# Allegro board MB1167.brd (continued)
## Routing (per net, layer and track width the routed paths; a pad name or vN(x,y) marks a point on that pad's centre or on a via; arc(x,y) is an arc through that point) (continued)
PB6: length 159.7
  TOP w0.127: v1(113.54,145.8) CN6.18 116.59,145.8 117.5,146.71 117.5,148.23 119.51,150.24 119.51,158.12 v1(122.43,161.04) ; R43.2 91.57,136.78 92.1,137.31 v1(92.1,137.85) ; v1(33.66,151.51) U3.7
  L4_SIG w0.102: v1(92.1,137.85) 92.1,138.84 92.58,139.32 92.58,140.21 95.12,142.75 96.39,142.75 97.28,143.64 108.08,143.64 110.87,146.43 112.9,146.43 v1(113.54,145.8)
  BOTTOM w0.127: v1(122.43,161.04) 117.86,165.61 117.86,167.89 115.09,170.66 42.27,170.66 39.88,168.28 39.88,161.67 35.81,157.61 35.81,152.4 R226.2 v1(33.66,151.51)
PB7: length 202.9
  TOP w0.127: U4.B5 83.3,139.69 83.69,140.08 84.33,140.08 84.58,139.83 85.22,139.83 85.47,139.57 87.51,139.57 v5(87.95,139.13) ; v1(88.39,56.13) 92.25,56.13 93.01,55.37 111.38,55.37 R301.2 112.27,52.45 111.38,51.56 ; v1(112.67,145.8) 112.67,144.17 112.27,143.76 111.56,143.76 111.05,143.26 CN6.21 ; v1(129.74,137.9) 129.97,138.13 129.97,145.8 128.8,146.96 v1(128.02,146.96)
  L4_SIG w0.102: v1(128.02,146.96) 123.47,146.96 121.72,145.21 113.33,145.21 112.75,145.8 v1(112.67,145.8) 111,145.8 106.81,141.6 97.03,141.6 92.84,137.41 89.92,137.41 88.27,139.06 88.01,139.06 v5(87.95,139.13) ; v1(88.39,56.13) 88.39,56.64 88.9,57.15 90.02,57.15 106.25,73.38 106.25,74.42 107.34,75.51 108.34,75.51 111.56,78.73 111.56,88.54 116.1,93.09 117.63,93.09 124.59,100.05 124.59,100.94 125.81,102.16 127.23,102.16 127.81,102.74 127.81,104.44 126.7,105.56 126.57,105.56 124.79,107.34 124.79,111.05 127.81,114.07 132.03,114.07 132.66,114.71 132.66,127.2 130.99,128.88 130.99,136.73 129.82,137.9 v1(129.74,137.9)
PB8: length 453.9
  TOP w0.127: v1(69.53,29.27) CN20.40 69.53,24.57 R190.2 ; v1(40.39,161.29) 40.64,161.54 R5.1 ; CN6.31 108.33,136.91 v1(108.08,136.65) 107.06,135.64 99.11,135.64 96.7,133.22 89.11,133.22 88.27,134.07 88.27,135.76 86.87,137.16 85.22,137.16 84.29,138.09 U4.A7 ; R195.1 123.19,23.11 123.19,24.64 122.94,24.89 122.17,24.89 v1(121.41,25.65)
  L4_SIG w0.102: v1(69.53,29.27) 69.53,34.28 68.83,34.98 53.8,34.98 53.47,35.31 v1(53.47,35.69) 53.47,36.42 54.42,37.38 75.39,37.38 116.64,78.63 116.64,86.94 131.42,101.73 131.42,106.1 133.83,108.51 136.07,108.51 141.22,113.67 142.93,113.67 146.3,117.04 153.67,117.04 155.57,118.95 155.57,134.11 154.18,135.51 154.18,146.81 151.89,149.1 151.89,153.16 v1(150.5,154.56) 150.11,154.94 150.11,156.97 147.7,159.38 127.13,159.38 126.36,160.15 121.79,160.15 119.63,162.31 108.58,162.31 106.3,160.02 103.5,160.02 103,159.51 v1(102.74,159.51) 102.49,159.51 100.46,157.48 98.81,157.48 97.66,158.62 96.39,158.62 94.36,160.66 83.44,160.66 81.92,162.18 66.55,162.18 65.79,161.42 40.51,161.42 v1(40.39,161.29)
  BOTTOM w0.127: v1(69.53,29.27) 69.53,28.77 75.95,22.35 94.74,22.35 96.01,23.62 118.75,23.62 120.78,25.65 v1(121.41,25.65) ; R290.1 53.72,35.43 v1(53.47,35.69) ; R183.1 148.21,154.6 T4.3 150.37,154.69 v1(150.5,154.56) ; v1(108.08,136.65) 107.57,137.16 107.57,154.05 105.03,156.59 105.03,158.24 103.76,159.51 v1(102.74,159.51)
PB9: length 411.9
  TOP w0.127: R191.2 70.8,24.45 CN20.38 v1(70.8,29.15) ; v5(86.49,140.68) 86.25,140.45 85.23,140.45 84.79,140.89 83.61,140.89 U4.B4 ; R3.1 v1(40.64,167.39) ; R189.1 127.33,24.97 v1(127.33,24.89) ; v1(113.54,148.34) CN6.14 116.97,148.34 119.13,150.5 119.13,158.5 v1(121.67,161.04)
  L4_SIG w0.089: 118.87,31.5 120.4,29.97
  L4_SIG w0.102: v1(121.67,161.04) 122.17,160.53 126.62,160.53 127.38,159.77 148.34,159.77 149.22,158.88 150.5,158.88 151.96,157.42 151.96,155.89 v1(151,154.94) ; v1(127.33,24.89) 125.83,26.39 124.43,26.39 122.07,28.75 121.62,28.75 120.4,29.97 ; v1(70.8,29.15) 70.8,29.65 69.98,30.48 69.98,34.42 69.14,35.26 54.56,35.26 v1(54.1,35.71) ; v5(86.49,140.68) 87.15,141.35 88.39,141.35 90.93,143.89 92.2,143.89 95.76,147.45 109.22,147.45 110.74,148.97 112.9,148.97 v1(113.54,148.34) ; 118.87,31.5 115.82,34.54 115.82,37.47 115.24,38.05 115.24,46.02 117.86,48.64 117.86,74.17 v1(116.59,75.44)
  BOTTOM w0.127: v1(127.33,24.89) 124.69,27.53 121.56,27.53 118.16,24.13 95.5,24.13 94.11,22.73 76.2,22.73 70.8,28.13 v1(70.8,29.15) ; v1(121.67,161.04) 117.35,165.35 117.35,167.64 114.81,170.18 43.43,170.18 v1(40.64,167.39) ; R298.1 152.53,154.35 T5.3 151.13,154.81 v1(151,154.94) ; R291.1 54.1,33.4 54.48,33.78 54.48,35.31 54.1,35.69 v1(54.1,35.71) ; v1(113.54,148.34) 113.77,148.34 117.08,145.02 117.08,144.28 123.7,137.67 123.7,118.59 116.79,111.68 116.79,75.69 116.59,75.49 v1(116.59,75.44)
PB10: length 110.3
  TOP w0.127: v1(43.36,135.56) 43.28,135.64 CN5.33 ; v5(73.21,133.69) U4.P12 ; R102.2 v1(34.8,107.57)
  L4_SIG w0.102: v5(73.21,133.69) 73.21,133.72 72.64,134.29 68.35,134.29 66.73,132.66 56.26,132.66 53.77,135.15 48.59,135.15 48.18,135.56 v1(43.36,135.56) 43.13,135.56 43,135.69 43,137.54 42.88,137.67 39.34,137.67 39.22,137.54 39.22,137.35 39.34,137.22 42.34,137.22 42.47,137.1 42.47,136.94 42.34,136.82 39.34,136.82 39.22,136.69 39.22,136.54 39.34,136.41 42.37,136.41 42.49,136.28 42.49,136.13 42.37,136 39.34,136 39.22,135.88 39.22,135.68 39.34,135.56 42.34,135.56 42.47,135.43 42.47,135.28 42.34,135.15 39.4,135.15 39.27,135.02 39.27,134.87 39.4,134.74 42.29,134.74 42.42,134.62 42.42,134.47 42.29,134.34 39.45,134.34 39.32,134.21 39.32,134.01 39.45,133.88 42.37,133.88 42.47,133.78 42.47,133.58 42.37,133.47 39.39,133.47 39.27,133.36 39.27,133.19 39.39,133.07 42.37,133.07 42.47,132.97 42.47,132.76 42.37,132.66 40.16,132.66 40.03,132.54 40.03,128.93 39.9,128.8 39.34,128.8 39.22,128.68 39.22,112.06 34.8,107.65 v1(34.8,107.57)
PB11: length 111.2
  TOP w0.127: v1(34.8,106.17) 35.43,105.54 R106.2 ; CN5.36 45.75,134.37 45.09,135.03 v1(44.25,135.03) ; v5(72.41,132.89) U4.R13
  L4_SIG w0.102: v1(34.8,106.17) 35.18,106.17 35.31,106.3 35.31,107.64 39.57,111.91 39.57,128.3 39.7,128.42 40.28,128.42 40.41,128.55 40.41,131.29 40.51,131.4 43.06,131.4 43.18,131.52 43.18,131.68 43.06,131.8 40.51,131.8 40.41,131.9 40.41,132.16 40.54,132.28 42.72,132.28 43.03,132.59 44.6,132.59 44.73,132.71 44.73,132.89 44.6,133.02 42.98,133.02 42.85,133.15 42.85,134.9 42.98,135.03 v1(44.25,135.03) 44.37,135.15 45.7,135.15 45.82,135.03 45.82,134.49 45.93,134.37 46.1,134.37 46.22,134.49 46.22,135.06 46.34,135.18 46.51,135.18 46.63,135.06 46.63,134.51 46.75,134.39 46.92,134.39 47.03,134.51 47.03,135.03 47.15,135.15 47.32,135.15 47.44,135.03 47.44,134.51 47.56,134.39 47.73,134.39 47.85,134.51 47.85,134.96 47.97,135.08 48.13,135.08 48.25,134.96 48.25,134.49 48.37,134.37 48.54,134.37 48.66,134.49 48.66,134.65 48.76,134.75 48.96,134.75 49.07,134.65 49.07,134.13 49.19,134.01 49.35,134.01 49.47,134.13 49.47,134.65 49.57,134.75 49.78,134.75 49.88,134.65 49.88,133.39 50,133.27 50.17,133.27 50.29,133.39 50.29,134.65 50.39,134.75 50.59,134.75 50.69,134.65 50.69,132.76 50.81,132.64 50.98,132.64 51.1,132.76 51.1,134.65 51.2,134.75 51.4,134.75 51.5,134.65 51.5,132.64 51.63,132.51 51.84,132.51 51.97,132.64 51.97,134.62 52.1,134.75 52.3,134.75 52.43,134.62 52.43,132.56 52.55,132.44 52.79,132.44 52.92,132.56 52.92,134.57 53.05,134.7 53.26,134.7 53.39,134.57 53.39,132.41 53.52,132.28 68.12,132.28 68.25,132.41 68.25,133.73 68.38,133.86 68.61,133.86 68.71,133.76 68.71,132.72 68.81,132.61 69.01,132.61 69.11,132.72 69.11,133.76 69.22,133.86 69.42,133.86 69.52,133.76 69.52,132.72 69.62,132.61 69.82,132.61 69.93,132.72 69.93,133.76 70.03,133.86 70.23,133.86 70.33,133.76 70.33,132.72 70.43,132.61 70.64,132.61 70.74,132.72 70.74,133.76 70.84,133.86 71.04,133.86 71.15,133.76 71.15,132.72 71.25,132.61 71.45,132.61 71.55,132.72 71.55,133.76 71.65,133.86 72.28,133.86 72.41,133.73 v5(72.41,132.89)
PB12: length 112.1
  TOP w0.127: v5(75.61,132.89) U4.L13 ; CN5.41 43.15,130.56 v1(43.41,130.3) ; R109.2 v1(34.8,104.9)
  L4_SIG w0.102: v1(34.8,104.9) 35.66,104.9 35.79,105.03 35.79,107.62 39.93,111.76 39.93,127.91 40.06,128.04 40.72,128.04 40.84,128.17 40.84,130.89 40.97,131.01 42.85,131.01 42.98,130.89 42.98,130.71 42.85,130.58 41.45,130.58 41.33,130.45 41.33,130.28 41.45,130.15 43.26,130.15 v1(43.41,130.3) 44.02,130.3 44.53,129.79 49.15,129.79 49.86,129.08 51.08,129.08 51.18,128.98 51.18,127.69 51.28,127.58 51.49,127.58 51.59,127.69 51.59,128.98 51.69,129.08 51.89,129.08 51.99,128.98 51.99,127.69 52.1,127.58 52.3,127.58 52.4,127.69 52.4,128.98 52.5,129.08 52.71,129.08 52.81,128.98 52.81,127.69 52.91,127.58 53.11,127.58 53.21,127.69 53.21,128.98 53.32,129.08 53.52,129.08 53.62,128.98 53.62,127.69 53.72,127.58 53.92,127.58 54.03,127.69 54.03,128.98 54.13,129.08 54.33,129.08 54.43,128.98 54.43,127.69 54.53,127.58 54.74,127.58 54.84,127.69 54.84,128.98 54.94,129.08 55.14,129.08 55.25,128.98 55.25,127.69 55.35,127.58 55.55,127.58 55.65,127.69 55.65,128.98 55.75,129.08 55.96,129.08 56.06,128.98 56.06,127.69 56.16,127.58 56.36,127.58 56.46,127.69 56.46,128.98 56.57,129.08 56.77,129.08 56.87,128.98 56.87,127.69 56.97,127.58 57.18,127.58 57.28,127.69 57.28,128.98 57.38,129.08 57.58,129.08 57.68,128.98 57.68,127.69 57.79,127.58 57.99,127.58 58.09,127.69 58.09,128.98 58.19,129.08 58.4,129.08 58.5,128.98 58.5,127.69 58.6,127.58 58.8,127.58 58.9,127.69 58.9,128.98 59,129.08 59.21,129.08 59.31,128.98 59.31,127.69 59.41,127.58 59.61,127.58 59.72,127.69 59.72,128.98 59.82,129.08 60.02,129.08 60.12,128.98 60.12,127.69 60.22,127.58 60.43,127.58 60.53,127.69 60.53,128.98 60.63,129.08 62.5,129.08 65.34,126.24 71.25,126.24 75.61,130.6 v5(75.61,132.89)
  BOTTOM w0.127: v1(43.41,130.3) 42.42,130.3 42.16,130.56
PB13: length 110.5
  TOP w0.127: R115.2 v1(34.8,103.63) ; U4.K14 76.44,132.12 76.44,130.53 v5(76.34,130.43) ; CN5.43 v1(43.41,129.29)
  L4_SIG w0.102: v1(34.8,103.63) 35.56,103.63 36.2,104.27 36.2,107.52 40.28,111.61 40.28,126.24 40.39,126.34 42.72,126.34 42.82,126.44 42.82,126.64 42.72,126.75 40.39,126.75 40.28,126.85 40.28,127.08 40.41,127.2 43,127.2 43.13,127.33 43.13,127.51 43,127.64 41.22,127.64 41.1,127.75 41.1,127.92 41.22,128.04 42.83,128.04 42.95,128.16 42.95,128.33 42.83,128.45 41.35,128.45 41.25,128.55 41.25,128.75 41.35,128.85 42.67,128.85 42.77,128.96 42.77,129.16 42.67,129.26 41.38,129.26 41.25,129.39 41.25,129.59 41.38,129.72 43.28,129.72 43.41,129.59 v1(43.41,129.29) 43.41,128.6 43.54,128.47 43.79,128.47 43.92,128.6 43.92,129.44 44.04,129.57 44.22,129.57 44.35,129.44 44.35,128.85 44.48,128.73 45.24,128.73 45.37,128.6 45.37,127.58 45.49,127.46 45.65,127.46 45.77,127.58 45.77,128.74 45.89,128.85 46.06,128.85 46.18,128.74 46.18,126.79 46.3,126.67 46.47,126.67 46.59,126.79 46.59,128.74 46.7,128.85 46.87,128.85 46.99,128.74 46.99,126.76 47.11,126.64 47.28,126.64 47.4,126.76 47.4,128.71 47.52,128.83 47.69,128.83 47.8,128.71 47.8,126.74 47.92,126.62 48.09,126.62 48.21,126.74 48.21,128.68 48.34,128.8 48.56,128.8 48.69,128.68 48.69,126.77 48.82,126.64 49.02,126.64 49.15,126.77 49.15,127.97 49.28,128.09 49.5,128.09 49.63,127.97 49.63,126.77 49.76,126.64 63.86,126.64 65.02,125.48 71.5,125.48 76.34,130.31 v5(76.34,130.43)
  BOTTOM w0.127: R259.2 v1(43.41,129.29)
PB14: length 113.9
  TOP w0.127: v5(72.41,132.09) U4.R14 ; v1(43.79,133.91) 43.79,134.14 43.56,134.37 CN5.35
  TOP w0.155: D6.D3 8.56,84.83 9.09,84.83 v1(9.23,84.69)
  L4_SIG w0.13: v1(43.79,133.91) 43.81,133.91 44.35,134.44 44.94,134.44 46.26,133.12 49.12,133.12 50.67,131.57 69.39,131.57 69.7,131.88 72.2,131.88 v5(72.41,132.09)
  BOTTOM w0.155: v1(43.79,133.91) 43.79,134.11 43.28,134.62 37.98,134.62 36.07,132.71 36.07,121.54 36.58,121.03 36.58,112.39 38.1,110.87 38.1,98.52 24.41,84.83 9.37,84.83 v1(9.23,84.69) 8.89,84.35 R288.2
PB15: length 113.8
  TOP w0.127: CN5.38 45.26,133.1 v1(44.45,133.91) ; v5(72.41,131.29) U4.R15
  TOP w0.155: v1(9.23,85.35) 9.09,85.21 8.56,85.21 D6.C3
  L4_SIG w0.13: v1(44.45,133.91) 44.45,133.93 44.58,134.06 44.78,134.06 46.1,132.74 48.97,132.74 50.52,131.19 69.55,131.19 69.86,131.5 72.2,131.5 v5(72.41,131.29)
  BOTTOM w0.155: R286.2 8.89,85.69 v1(9.23,85.35) 9.37,85.21 24.25,85.21 37.72,98.68 37.72,110.74 36.27,112.19 36.27,120.83 35.76,121.34 35.76,132.94 37.82,135 43.43,135 44.45,133.99 v1(44.45,133.91)
PC0: length 111.3
  TOP w0.127: CN5.11 v1(43.43,149.61) ; v5(74.81,142.49) U4.M2 ; R125.2 29.34,100.2 v1(29.34,100.33)
  L4_SIG w0.102: v5(74.81,142.49) 74.42,142.88 73.92,142.88 73.65,143.14 73.65,143.36 73.2,143.81 69.8,143.81 68.71,144.91 65.66,144.91 64.39,146.18 53.98,146.18 51.18,148.97 44.07,148.97 v1(43.43,149.61) 41.53,149.61 41.4,149.48 41.4,149.22 41.53,149.1 42.6,149.1 42.72,148.97 42.72,148.72 42.6,148.59 40.49,148.59 40.36,148.46 40.36,148.21 40.49,148.08 42.67,148.08 42.8,147.96 42.8,147.7 42.67,147.57 40.45,147.57 40.32,147.45 40.32,147.18 40.42,147.08 42.65,147.08 42.77,146.96 42.77,146.8 42.65,146.68 40.12,146.68 40.01,146.56 40.01,145.29 37.47,142.75 37.47,139.06 36.7,138.3 36.7,129.41 37.47,128.65 37.47,114.94 36.62,114.09 36.47,114.09 35.88,114.68 35.74,114.68 35.59,114.54 35.59,114.39 36.19,113.8 36.19,113.66 36.04,113.51 35.9,113.51 35.31,114.11 35.16,114.11 35.02,113.96 35.02,113.82 35.61,113.23 35.61,113.08 32.21,109.68 32.21,104.09 31.5,103.38 31.5,101.98 29.84,100.33 v1(29.34,100.33)
PC1: length 37.8
  TOP w0.127: CN5.16 v1(44.83,147.07) ; U4.M3 v5(74.81,141.69)
  L4_SIG w0.102: v5(74.81,141.69) 74.38,142.11 67.01,142.11 65.91,143.21 61.14,143.21 60.07,144.27 52.73,144.27 49.94,147.07 v1(44.83,147.07)
  BOTTOM w0.127: SB22.1 SB31.1 45.34,147.57 v1(44.83,147.07)
PC2: length 39
  TOP w0.127: U4.M4 v5(74.81,140.89) ; CN5.23 v1(43.41,141.99)
  L4_SIG w0.102: v5(74.81,140.89) 74.39,140.46 71.37,140.46 69.7,138.79 58.88,138.79 56.11,141.55 43.84,141.55 v1(43.41,141.99)
  BOTTOM w0.127: R241.1 SB38.1 43.03,141.6 v1(43.41,141.99)
PC3: length 43.8
  TOP w0.127: U4.L4 v5(75.61,140.89) ; CN5.27 v1(43.43,139.45)
  L4_SIG w0.102: v5(75.61,140.89) 75.61,140.89 75.18,140.46 75.18,138.3 74.93,138.05 73.53,138.05 72.67,137.19 68.78,137.19 68.33,136.73 67.69,136.73 66.52,137.9 57.56,137.9 55.5,139.95 43.94,139.95 v1(43.43,139.45)
  BOTTOM w0.127: v1(43.43,139.45) 43.79,139.8 45.62,139.8 SB41.1 SB44.1
PC4: length 37.6
  TOP w0.127: v5(74.01,140.09) U4.N5 ; v1(43.43,140.08) 42.8,140.72 CN5.25
  L4_SIG w0.102: v5(74.01,140.09) 73.65,139.73 71.3,139.73 69.93,138.35 58.12,138.35 56.21,140.26 43.61,140.26 v1(43.43,140.08)
  BOTTOM w0.127: v1(43.43,140.08) 42.42,140.08 42.16,139.83 42.16,138.56
PC5: length 36.8
  TOP w0.102: U4.P5 73.19,140.11 71.63,140.11
  TOP w0.127: 71.63,140.11 69.49,140.11 67.94,138.56 63.58,138.56 53.04,128.02 CN5.46 v1(44.83,128.02)
  BOTTOM w0.127: SB53.1 SB55.1 v1(44.83,128.02)
PC13: length 251.5
  TOP w0.127: CN6.6 114.3,153.42 113.46,152.58 v1(113.46,152.53) ; R180.2 49.53,20.7 50.8,19.43 50.8,17.65 53.98,14.48 53.98,11.56 R216.2 55.5,12.06 57.91,12.06 61.79,15.94 63.82,15.94 66.8,18.92 82.17,18.92 83.63,20.38 91.76,20.38 94.79,23.42 94.79,48.08 v1(92.58,50.29) ; U4.D1 v5(82.01,143.29)
  L4_SIG w0.102: v1(113.46,152.53) 113.26,152.53 112.62,151.89 110.41,151.89 109.75,152.55 96.16,152.55 92.58,148.97 91.06,148.97 90.17,148.08 85.75,148.08 82.01,144.34 v5(82.01,143.29)
  BOTTOM w0.127: v1(92.58,50.29) 113.16,70.87 115.6,70.87 118.82,74.09 v1(118.82,83.72) 118.82,96.65 120.19,98.02 120.19,112.55 125.27,117.63 125.27,139.01 119.14,145.15 119.14,146.57 113.46,152.25 v1(113.46,152.53)
PC14: length 9.4
  TOP w0.203: U4.E1 80.64,143.05 80.64,144.4 82.3,146.05 82.3,147.19 82.68,147.57 83.31,147.57 v1(83.44,147.7) 84.12,148.39 R18.2
  BOTTOM w0.127: v1(83.44,147.7) 83.44,147.96 83.95,148.46 SB25.1
PC15: length 8.8
  TOP w0.203: R17.2 80.31,148.41 v1(80.98,147.75) 81.66,147.07 81.66,146.18 80.14,144.65 80.14,143.01 U4.F1
  BOTTOM w0.127: v1(80.98,147.75) 80.9,147.75 80.26,148.39 SB26.1
PD4: length 127.4
  TOP w0.102: U14.A2 68.33,79.69 68.33,80.27 v5(68.71,80.64) ; U9.G2 75.36,105.92 73.57,105.92 73.03,105.37 v4(72.9,105.37)
  TOP w0.127: CN11.28 v3(103.38,100.89) ; v5(82.01,134.49) U4.D11
  L4_SIG w0.102: v4(72.9,105.37) 73.49,104.78 77.06,104.78 77.57,104.26 77.8,104.03 77.8,103.68 80.09,101.4 81.48,101.4 82.06,101.98 98.76,101.98 99.14,101.6 102.67,101.6 v3(103.38,100.89)
  BOTTOM w0.127: v5(68.71,80.64) 68.71,80.92 68.58,81.05 67.18,81.05 67.06,81.18 67.06,81.38 67.18,81.5 68.53,81.5 68.66,81.63 68.66,81.88 68.53,82.01 67.18,82.01 67.06,82.14 67.06,82.43 67.18,82.56 67.72,82.56 67.84,82.69 67.84,82.94 67.72,83.07 67.18,83.07 67.06,83.2 67.06,83.69 65.84,84.91 65.84,100.28 70.92,105.37 71.22,105.37 71.35,105.5 71.35,105.84 71.48,105.97 71.73,105.97 71.86,105.84 71.86,105.5 71.99,105.37 72.29,105.37 72.42,105.5 72.42,106.76 72.54,106.88 73.56,106.88 73.69,106.76 73.69,106.53 73.56,106.4 73.03,106.4 72.9,106.27 72.9,106.05 73.03,105.92 73.46,105.92 73.58,105.79 73.58,105.5 73.46,105.37 v4(72.9,105.37) ; v5(82.01,134.49) 82.05,134.49 82.42,134.11 83.82,134.11 88.01,129.92 88.01,113.28 100.97,100.33 102.82,100.33 v3(103.38,100.89)
PD5: length 63.3
  TOP w0.127: v5(82.81,135.29) U4.C10 ; CN11.26 v3(103.38,102.16) ; R107.2 v3(90.04,103.5)
  L4_SIG w0.102: v3(90.04,103.5) 98.42,103.5 99.06,102.87 103.28,102.87 103.38,102.77 v3(103.38,102.16)
  BOTTOM w0.127: v3(103.38,102.16) 102.79,101.57 101.24,101.57 88.77,114.05 88.77,131.83 87.71,132.89 86.05,132.89 85.66,133.29 85.66,133.54 84.07,135.13 82.97,135.13 v5(82.81,135.29)
PD7: length 75
  TOP w0.127: v5(87.2,134.21) 87.02,134.21 86.74,134.49 84.96,134.49 84.57,134.89 U4.A11 ; v3(78.49,109.47) 78.61,109.6 R91.2 ; CN11.24 v3(103.38,103.43)
  L4_SIG w0.102: v3(103.38,103.43) 102.79,104.01 99.06,104.01 98.63,104.44 84.02,104.44 82.3,106.17 80.14,106.17 78.11,108.2 78.11,109.09 v3(78.49,109.47)
  BOTTOM w0.127: v3(103.38,103.43) 102.82,102.87 101.35,102.87 89.53,114.68 89.53,132.21 87.62,134.12 87.29,134.12 v5(87.2,134.21)
PE0: length 140.8
  TOP w0.102: v5(89.46,75.01) U13.K9 ; U14.A1 70.26,80.11 71.25,79.12 v5(71.25,76.07)
  TOP w0.127: v5(86.49,137.92) 86.36,137.79 85.63,137.79 85.25,138.18 85.22,138.18 84.51,138.89 U4.A6 ; CN11.25 v3(101.98,102.16)
  L4_SIG w0.102: v5(71.25,76.07) 76.45,76.07 76.71,75.82 v1(80.77,75.82) 81.13,76.17 84.18,76.17 84.7,76.7 84.7,76.89 84.91,77.1 87.61,77.1 87.81,76.89 87.81,76.65 88.17,76.3 88.57,76.3 88.7,76.17 88.7,75.72 88.82,75.59 90.02,75.59 90.14,75.46 90.14,74.19 90.02,74.07 89.59,74.07 89.46,74.19 v5(89.46,75.01)
  BOTTOM w0.127: v5(86.49,137.92) 86.49,137.72 86.79,137.41 86.79,134.06 87.11,133.74 87.44,133.74 89.15,132.03 89.15,114.43 101.42,102.16 v3(101.98,102.16) 102.67,102.16 103.25,102.74 103.73,102.74 104.32,102.16 104.32,92.23 103.45,91.36 90.73,91.36 84.89,85.52 84.89,83.03 85.43,82.49 85.43,82.19 85.34,82.1 85.34,81.78 85.43,81.69 85.43,81.39 85.34,81.3 85.34,80.98 85.43,80.89 85.43,80.59 85.34,80.5 85.34,80.01 85.22,79.89 84.94,79.89 84.81,79.76 84.81,79.51 84.94,79.38 85.55,79.38 85.67,79.25 85.67,79.04 85.55,78.92 84.43,78.92 84.3,78.79 84.3,78.51 84.43,78.38 85.55,78.38 85.67,78.26 85.67,78 85.55,77.88 84.56,77.88 84.43,77.75 84.43,76 84.31,75.87 84.05,75.87 83.93,76 83.93,77.75 83.8,77.88 83.54,77.88 83.42,77.75 83.42,76 83.29,75.87 83.04,75.87 82.91,76 82.91,77.75 82.78,77.88 82.55,77.88 82.42,77.75 82.42,75.95 82.3,75.82 82.04,75.82 81.92,75.95 81.92,76.99 81.79,77.11 81.54,77.11 81.41,76.99 81.41,75.95 81.28,75.82 v1(80.77,75.82)
PE1: length 145.6
  TOP w0.102: U14.B2 67.56,79.71 67.56,82.42 67.94,82.8 ; v5(89.46,82.5) U13.K1
  TOP w0.127: v5(68.83,83.69) 67.94,82.8 ; v5(87.38,138.05) 87.37,138.05 87.37,138.56 86.74,139.19 85.22,139.19 84.96,139.45 84.43,139.45 84.19,139.69 U4.A5 ; CN11.23 v3(101.98,103.43)
  L4_SIG w0.102: v5(89.46,82.5) 89.46,80.37 89.33,80.24 88.67,80.24 88.54,80.37 88.54,80.49 88.67,80.62 88.9,80.62 89.03,80.75 89.03,80.9 88.9,81.03 88.77,81.03 88.65,81.15 88.65,81.31 88.77,81.43 88.98,81.43 89.1,81.55 89.1,81.72 88.98,81.84 88.69,81.84 88.57,81.96 88.57,82.13 88.69,82.25 88.9,82.25 89.03,82.37 89.03,82.75 89.15,82.88 89.46,82.88 89.59,83.01 89.59,83.11 89.46,83.24 88.7,83.24 88.57,83.36 88.57,83.54 88.7,83.67 89.44,83.67 89.56,83.79 89.56,83.95 89.44,84.07 88.37,84.07 88.24,83.95 88.24,82.09 88.11,81.97 87.58,81.97 87.45,82.09 87.45,83.85 87.33,83.97 87.12,83.97 86.99,83.85 86.99,83.21 86.89,83.11 86.69,83.11 86.59,83.21 86.59,83.67 86.46,83.79 85.47,83.79 85.34,83.92 v1(85.34,83.95) 85.17,83.77 68.91,83.77 v5(68.83,83.69)
  BOTTOM w0.127: v5(87.38,138.05) 87.38,137.16 89.92,134.62 89.92,115 101.21,103.71 101.46,103.71 101.74,103.43 v3(101.98,103.43) 102.54,103.43 103.12,104.01 104.09,104.01 104.72,103.38 104.72,102.93 104.85,102.8 105.28,102.8 105.41,102.67 105.41,102.42 105.28,102.29 104.85,102.29 104.72,102.16 104.72,101.91 104.85,101.78 105.28,101.78 105.41,101.66 105.41,101.4 105.28,101.28 104.85,101.28 104.72,101.15 104.72,100.89 104.85,100.77 105.28,100.77 105.41,100.64 105.41,100.39 105.28,100.26 104.85,100.26 104.72,100.13 104.72,99.88 104.85,99.75 105.28,99.75 105.41,99.62 105.41,99.37 105.28,99.24 104.85,99.24 104.72,99.12 104.72,98.86 104.85,98.74 105.28,98.74 105.41,98.61 105.41,98.35 105.28,98.23 104.85,98.23 104.72,98.1 104.72,97.85 104.85,97.72 105.28,97.72 105.41,97.59 105.41,97.34 105.28,97.21 104.85,97.21 104.72,97.08 104.72,96.83 104.85,96.7 105.28,96.7 105.41,96.58 105.41,96.32 105.28,96.2 104.85,96.2 104.72,96.07 104.72,92 103.66,90.93 91.06,90.93 89.13,89 89.13,88.82 89.8,88.15 89.8,87.97 89.62,87.79 89.44,87.79 88.77,88.46 88.59,88.46 88.41,88.28 88.41,88.1 89.82,86.69 89.82,86.51 89.64,86.33 89.46,86.33 88.05,87.74 87.87,87.74 87.69,87.56 87.69,87.38 88.7,86.37 88.7,86.19 88.52,86.01 88.34,86.01 87.33,87.02 87.15,87.02 86.97,86.84 86.97,86.66 87.35,86.28 87.35,86.1 87.17,85.92 86.99,85.92 86.61,86.3 86.43,86.3 85.34,85.22 v1(85.34,83.95)
PF6: length 53.2
  TOP w0.127: v1(43.43,151.96) 43.42,151.96 43.23,152.15 CN5.7 37.21,152.15 37.08,152.02 37.08,142.11 36.96,141.99 31.62,141.99 31.5,142.11 31.5,146.23 30.78,146.94 v1(30.73,146.94) ; R24.2 65.79,147.83 65.66,147.7 64.14,147.7 v1(63.88,147.96)
  L4_SIG w0.102: v1(43.43,151.96) 43.45,151.94 43.64,151.94 43.94,151.64 44.81,151.64 45.76,150.69 51.37,150.69 54.74,147.32 63.25,147.32 v1(63.88,147.96)
  BOTTOM w0.127: v1(30.73,146.94) 31.11,146.56 R237.2
PF7: length 51.4
  TOP w0.127: v1(64.77,148.21) 65.24,148.21 65.88,148.84 R22.2 ; v1(30.73,151) 32.51,151 32.64,151.13 32.64,151.51 32.51,151.64 31.37,151.64 31.24,151.76 31.24,152.53 32.51,153.8 34.8,153.8 38.35,157.35 48.26,157.35 49.53,156.08 49.53,152.65 v1(49.4,152.53) 49.02,152.15 CN5.8
  L4_SIG w0.102: v1(64.77,148.21) 64.57,148.41 54.86,148.41 50.75,152.53 v1(49.4,152.53)
  BOTTOM w0.127: R228.1 30.48,151.26 v1(30.73,151)
PF8: length 55.2
  TOP w0.127: v1(30.73,146.05) 30.73,141.6 30.86,141.48 37.47,141.48 37.59,141.6 37.59,149.4 37.72,149.53 38.48,149.53 38.61,149.4 38.61,146.18 38.99,145.8 CN5.17 v1(43.41,145.8) ; v1(64.52,139.57) 65.02,139.06 R41.2
  L4_SIG w0.102: v1(64.52,139.57) 64.52,139.85 63.02,141.35 60.99,141.35 59.33,143 51.87,143 49.71,145.16 44.04,145.16 v1(43.41,145.8)
  BOTTOM w0.127: v1(30.73,146.05) 30.23,146.56 R238.1
PF9: length 52.2
  TOP w0.127: CN5.12 v1(48.82,149.61) 50.16,150.95 50.16,156.08 48.51,157.73 38.2,157.73 34.64,154.18 32.13,154.18 30.73,152.78 v1(30.73,151.76) ; v1(65.15,147.19) 65.53,146.81 R26.2
  L4_SIG w0.102: v1(48.82,149.61) 51.31,149.61 54.36,146.56 64.52,146.56 v1(65.15,147.19)
  BOTTOM w0.127: R227.2 31.24,151.26 v1(30.73,151.76)
PF10: length 107.1
  TOP w0.127: JP24.2 40.39,93.98 R302.2 38.35,93.98 37.21,95.12 37.21,105.03 37.85,105.66 37.85,114.3 33.53,118.62 33.53,119.38 v1(33.91,119.76) ; CN5.9 v1(43.43,150.88) ; v5(73.66,145.03) 73.79,145.03 74.8,144.02 75.56,144.02 76.01,143.57 U4.L1
  L4_SIG w0.102: v5(73.66,145.03) 72.9,145.03 70.23,147.7 64.52,147.7 63.75,146.94 54.61,146.94 51.31,150.24 44.07,150.24 v1(43.43,150.88) 40.77,150.88 36.83,146.94 36.83,145.54 34.67,143.38 34.67,120.52 v1(33.91,119.76)
PF11: length 109.6
  TOP w0.102: 90.26,74.66 U13.J9
  TOP w0.127: v3(54.74,113.16) 55.24,113.16 55.68,113.59 CN10.8 ; 90.26,74.66 90.26,72.83 90.81,72.29 v1(90.81,70.79) ; R51.2 v1(64.52,124.59)
  L4_SIG w0.102: v1(90.81,70.79) 90.63,70.79 89.03,69.19 66.47,69.19 51.31,84.35 51.31,111.84 53.14,113.67 53.85,113.67 54.36,113.16 v3(54.74,113.16)
  BOTTOM w0.127: v3(54.74,113.16) 57.48,113.16 58.15,113.83 58.15,114.01 57.97,114.2 57.97,114.38 58.15,114.56 58.33,114.56 58.51,114.37 58.69,114.37 58.87,114.55 58.87,114.73 58.68,114.92 58.68,115.1 58.86,115.28 59.04,115.28 59.23,115.09 59.41,115.09 59.59,115.27 59.59,115.45 59.4,115.64 59.4,115.82 59.58,116 59.76,116 59.95,115.81 60.13,115.81 60.31,115.99 60.31,116.17 60.12,116.36 60.12,116.54 60.3,116.72 60.48,116.72 60.67,116.53 60.85,116.53 61.03,116.71 61.03,116.89 60.84,117.07 60.84,117.25 61.02,117.43 61.2,117.43 61.39,117.25 61.57,117.25 61.75,117.43 61.75,117.61 61.56,117.79 61.56,117.97 61.74,118.15 61.92,118.15 62.11,117.96 62.29,117.96 62.47,118.14 62.47,118.32 62.28,118.51 62.28,118.69 62.46,118.87 62.64,118.87 62.83,118.68 63.01,118.68 63.19,118.86 63.19,119.04 63,119.23 63,119.41 63.18,119.59 63.36,119.59 63.55,119.4 63.73,119.4 64.06,119.74 64.06,124.13 v1(64.52,124.59)
PG6: length 51.2
  TOP w0.127: SB11.1 77.98,123.83 78.79,124.64 78.79,127.33 77.11,129.01 v3(77.11,129.29) 77.11,129.44 77.47,129.79 77.47,131.55 U4.J15 ; CN5.51 v1(43.33,124.21)
  L4_SIG w0.102: v3(77.11,129.29) 77.11,128.8 74.68,126.36 74.68,123.7 73.91,122.94 64.01,122.94 62.48,124.46 49.91,124.46 49.2,123.75 44.65,123.75 44.2,124.21 v1(43.33,124.21)
PG7: length 47
  TOP w0.127: U4.J14 77.24,132.12 77.24,130.75 77.2,130.71 77.2,130.13 76.45,129.38 v3(76.45,128.91) 77.98,127.38 SB10.1 ; CN5.47 v1(43.41,126.75)
  L4_SIG w0.102: v3(76.45,128.91) 74.3,126.75 74.3,124.21 73.53,123.44 64.01,123.44 61.98,125.48 45.62,125.48 44.86,126.24 43.92,126.24 v1(43.41,126.75)
PG8: length 120.6
  TOP w0.102: v5(90.68,82.36) U13.J1
  TOP w0.127: v3(54.99,92.38) 54.99,92.5 55.76,93.27 CN10.40 ; R61.2 79.63,122.68 79.02,122.07 v1(78.99,122.07)
  L4_SIG w0.102: v3(54.99,92.38) 55.22,92.38 55.35,92.25 55.35,91.95 55.42,91.87 55.7,91.87 55.78,91.95 55.78,92.25 55.91,92.38 56.1,92.38 56.2,92.27 56.2,91.91 56.32,91.8 56.49,91.8 56.6,91.91 56.6,92.27 56.71,92.38 56.91,92.38 57.01,92.27 57.01,92.02 57.11,91.92 57.32,91.92 57.42,92.02 57.42,92.27 57.52,92.38 57.72,92.38 57.82,92.27 57.82,92.02 57.93,91.92 58.13,91.92 58.23,92.02 58.23,92.27 58.33,92.38 58.54,92.38 58.64,92.27 58.64,92.02 58.74,91.92 58.94,91.92 59.04,92.02 59.04,92.27 59.14,92.38 59.35,92.38 59.45,92.27 59.45,92.02 59.55,91.92 59.75,91.92 59.86,92.02 59.86,92.27 59.96,92.38 60.16,92.38 60.26,92.27 60.26,92.02 60.36,91.92 60.57,91.92 60.67,92.02 60.67,92.27 60.77,92.38 60.97,92.38 61.08,92.27 61.08,92.02 61.18,91.92 61.38,91.92 61.48,92.02 61.48,92.27 61.58,92.38 61.79,92.38 61.89,92.27 61.89,92.02 61.99,91.92 62.19,91.92 62.29,92.02 62.29,92.27 62.4,92.38 62.6,92.38 62.7,92.27 62.7,92.02 62.8,91.92 63.01,91.92 63.11,92.02 63.11,92.27 63.21,92.38 63.41,92.38 63.51,92.27 63.51,92.02 63.62,91.92 63.82,91.92 63.92,92.02 63.92,92.27 64.02,92.38 64.22,92.38 64.33,92.27 64.33,92.02 64.43,91.92 64.63,91.92 64.73,92.02 64.73,92.27 64.83,92.38 65.04,92.38 65.14,92.27 65.14,92.02 65.24,91.92 65.44,91.92 65.55,92.02 65.55,92.27 65.65,92.38 65.85,92.38 65.95,92.27 65.95,92.02 66.05,91.92 66.26,91.92 66.36,92.02 66.36,92.27 66.46,92.38 66.66,92.38 66.76,92.27 66.76,92.02 66.87,91.92 67.07,91.92 67.17,92.02 67.17,92.27 67.27,92.38 67.48,92.38 67.58,92.27 67.58,92.02 67.68,91.92 67.88,91.92 67.98,92.02 67.98,92.27 68.09,92.38 68.29,92.38 68.39,92.27 68.39,92.02 68.49,91.92 68.7,91.92 68.8,92.02 68.8,92.27 68.9,92.38 69.1,92.38 69.2,92.27 69.2,92.02 69.3,91.92 69.51,91.92 69.61,92.02 69.61,92.27 69.71,92.38 69.91,92.38 70.02,92.27 70.02,92.02 70.12,91.92 70.32,91.92 70.42,92.02 70.42,92.27 70.52,92.38 70.73,92.38 70.83,92.27 70.83,92.02 70.93,91.92 71.13,91.92 71.24,92.02 71.24,92.27 71.34,92.38 71.54,92.38 71.64,92.27 71.64,92.02 71.74,91.92 71.95,91.92 72.05,92.02 72.05,92.27 72.15,92.38 72.35,92.38 72.45,92.27 72.45,92.02 72.56,91.92 72.76,91.92 72.86,92.02 72.86,92.27 72.96,92.38 73.17,92.38 73.27,92.27 73.27,92.02 73.37,91.92 73.57,91.92 73.67,92.02 73.67,92.27 73.78,92.38 73.98,92.38 74.08,92.27 74.08,92.02 74.18,91.92 74.38,91.92 74.49,92.02 74.49,92.27 74.59,92.38 74.79,92.38 74.89,92.27 74.89,92.02 74.99,91.92 75.2,91.92 75.3,92.02 75.3,92.27 75.4,92.38 75.6,92.38 75.71,92.27 75.71,92.02 75.81,91.92 76.01,91.92 76.11,92.02 76.11,92.27 76.21,92.38 76.42,92.38 76.52,92.27 76.52,92.02 76.62,91.92 76.82,91.92 76.92,92.02 76.92,92.27 77.03,92.38 77.23,92.38 77.33,92.27 77.33,92.02 77.43,91.92 77.64,91.92 77.74,92.02 77.74,92.27 77.84,92.38 78.04,92.38 78.14,92.27 78.14,92.02 78.25,91.92 78.45,91.92 78.55,92.02 78.55,92.27 78.65,92.38 78.86,92.38 78.96,92.27 78.96,92.02 79.06,91.92 79.26,91.92 79.36,92.02 79.36,92.27 79.46,92.38 79.67,92.38 79.77,92.27 79.77,92.02 79.87,91.92 80.07,91.92 80.18,92.02 80.18,92.27 80.28,92.38 80.48,92.38 80.58,92.27 80.58,92.02 80.68,91.92 80.89,91.92 80.99,92.02 80.99,92.27 81.09,92.38 81.29,92.38 81.4,92.27 81.4,92.02 81.5,91.92 81.7,91.92 81.8,92.02 81.8,92.27 81.9,92.38 82.11,92.38 82.21,92.27 82.21,92.02 82.31,91.92 82.51,91.92 82.61,92.02 82.61,92.27 82.72,92.38 82.92,92.38 83.02,92.27 83.02,92.02 83.12,91.92 83.33,91.92 83.43,92.02 83.43,92.27 83.53,92.38 83.73,92.38 83.83,92.27 83.83,92.02 83.94,91.92 84.14,91.92 84.24,92.02 84.24,92.27 84.34,92.38 84.54,92.38 84.65,92.27 84.65,92.02 84.75,91.92 84.95,91.92 85.05,92.02 85.05,92.27 85.15,92.38 85.36,92.38 85.46,92.27 85.46,92.02 85.56,91.92 85.76,91.92 85.87,92.02 85.87,92.27 85.97,92.38 86.17,92.38 86.27,92.27 86.27,92.02 86.37,91.92 86.58,91.92 86.68,92.02 86.68,92.27 86.78,92.38 86.98,92.38 87.08,92.27 87.08,92.02 87.19,91.92 87.39,91.92 87.49,92.02 87.49,92.27 87.59,92.38 87.8,92.38 87.9,92.27 87.9,92.02 88,91.92 88.2,91.92 88.3,92.02 88.3,92.27 88.41,92.38 90.5,92.38 90.68,92.2 v5(90.68,82.36)
  BOTTOM w0.127: v3(54.99,92.38) 55.04,92.38 56.77,94.11 57.11,94.11 77.47,114.47 77.47,121.22 77.6,121.35 78.74,121.35 78.87,121.48 78.87,121.94 v1(78.99,122.07)
PG9: length 204.2
  TOP w0.127: CN6.17 111.15,145.8 111.86,146.51 v1(111.86,147.07) ; R193.2 v1(119.63,21.34) ; v5(82.01,136.09) U4.D9
  L4_SIG w0.089: 116.08,31.5 116.84,30.73 116.84,29.21 117.47,28.57 117.47,26.67
  L4_SIG w0.102: v1(128.27,151.23) 127.38,150.34 118.77,150.34 115.01,146.58 113.26,146.58 112.78,147.07 v1(111.86,147.07) 111,147.07 108.08,144.15 95.76,144.15 92.46,140.84 90.42,140.84 89.66,140.08 87.5,140.08 86.87,139.45 86.36,139.45 85.7,138.79 85.65,138.79 85.34,138.48 85.34,137.03 84.76,136.45 82.37,136.45 v5(82.01,136.09) ; v1(119.63,21.34) 119.63,22.25 117.09,24.79 117.09,25.27 117.47,25.65 117.47,26.67 ; v1(134.11,106.22) 133.3,105.41 133.3,101.22 129.95,97.87 128.98,97.87 117.88,86.77 117.88,78.05 115.57,75.74 115.57,50.04 113.03,47.5 113.03,34.54 116.08,31.5
  BOTTOM w0.127: v1(128.27,151.23) 130.81,148.69 130.81,128.78 133.73,125.86 133.73,125.25 135.08,123.9 135.08,120.47 133.53,118.92 133.53,106.81 133.93,106.41 133.93,106.41 v1(134.11,106.22)
PG10: length 117
  TOP w0.127: CN11.27 v1(101.98,100.89) ; U4.C8 v5(82.81,136.89) ; R147.2 70.36,67.94 v1(70.33,67.92)
  L4_SIG w0.102: v1(101.98,100.89) 101.98,100.38 102.11,100.25 104.88,100.25 105,100.13 105,92.43 99.01,86.44 99.01,81.61 98.37,80.98 98.37,74.42 98.16,74.21 98.02,74.21 97.68,74.55 97.54,74.55 97.39,74.41 97.39,74.26 97.73,73.92 97.73,73.78 97.59,73.64 97.45,73.64 97.11,73.98 96.96,73.98 96.82,73.83 96.82,73.69 97.16,73.35 97.16,73.21 97.01,73.06 96.87,73.06 96.53,73.4 96.39,73.4 96.24,73.26 96.24,73.11 96.58,72.77 96.58,72.63 96.44,72.49 96.3,72.49 95.96,72.83 95.81,72.83 95.67,72.68 95.67,72.54 96.01,72.2 96.01,72.06 95.35,71.4 94.01,71.4 90.53,67.92 v1(70.33,67.92)
  BOTTOM w0.127: v1(101.98,100.89) 101.17,100.89 88.38,113.68 88.38,130.12 85.09,133.41 85.09,133.6 83.82,134.87 82.65,134.87 82.42,135.1 82.42,136.5 v5(82.81,136.89)
PG11: length 35.9
  TOP w0.127: v1(111.86,135.64) CN6.33 109.33,134.98 99.44,134.98 97.31,132.84 89.03,132.84 87.88,133.99 87.88,135.76 86.78,136.87 84.93,136.87 84.89,136.83 84.42,136.83 84.34,136.91 83.59,136.91 U4.B8
  BOTTOM w0.127: R252.1 110.49,135.76 SB46.1 111.73,135.76 v1(111.86,135.64)
PG12: length 209.5
  TOP w0.127: R215.1 105.54,18.41 105.54,22.48 107.95,24.89 v1(107.95,30.86) ; U4.C7 v5(82.01,138.49) ; v1(111.86,148.34) 111.86,147.83 111.1,147.07 CN6.15
  L4_SIG w0.102: v5(82.01,138.49) 82.45,138.05 82.93,138.05 85.09,140.21 86.61,140.21 87.25,140.84 89.28,140.84 91.19,142.75 92.08,142.75 96.14,146.81 109.35,146.81 110.87,148.34 v1(111.86,148.34) 112.88,148.34 113.49,147.73 114.83,147.73 118.26,151.16 127.41,151.16 v1(128.37,152.12) ; v1(134.11,106.86) 132.87,105.61 132.87,102.26 117.45,86.84 117.45,78.05 115.19,75.79 115.19,50.2 112.65,47.66 112.65,39.12 107.95,34.42 v1(107.95,30.86)
  BOTTOM w0.127: v1(128.37,152.12) 131.19,149.3 131.19,129.29 135.43,125.04 135.43,120.22 133.88,118.67 133.88,107.09 v1(134.11,106.86)
PG13: length 34.4
  TOP w0.127: U4.B3 83.58,141.66 83.58,142.25 83.82,142.49 88.14,142.49 88.39,142.75 102.62,142.75 104.65,140.72 CN6.25 111.15,140.72 111.86,141.43 v1(111.86,141.99)
  BOTTOM w0.127: R243.1 112.5,141.35 v1(111.86,141.99)
PG14: length 31.6
  TOP w0.127: U4.A4 84.43,140.49 84.72,140.2 87.52,140.2 88.96,138.75 92.33,138.75 93.54,137.54 106.93,137.54 107.57,138.18 CN6.29 111.15,138.18 111.86,138.89 111.86,139.42 v1(111.89,139.45)
  BOTTOM w0.127: v1(111.89,139.45) 111.51,139.83 111,139.83 R244.1
PG15: length 116.4
  TOP w0.102: v5(89.06,76.74) U13.K7
  TOP w0.127: CN11.19 v3(101.98,105.97) ; R44.2 91.69,134.87 v3(91.69,134.77)
  BOTTOM w0.127: v3(91.69,134.77) 91.44,134.52 91.44,116.03 101.5,105.97 v3(101.98,105.97) 102.67,105.97 103.25,106.55 104.52,106.55 105.79,105.28 105.79,95.85 105.66,95.72 105.26,95.72 105.13,95.59 105.13,95.34 105.26,95.21 105.66,95.21 105.79,95.08 105.79,94.83 105.66,94.7 105.26,94.7 105.13,94.58 105.13,94.32 105.26,94.19 105.66,94.19 105.79,94.07 105.79,93.81 105.66,93.69 105.26,93.69 105.13,93.56 105.13,93.24 105.26,93.11 105.64,93.11 105.77,92.99 105.77,92.73 105.64,92.61 105.26,92.61 105.13,92.48 105.13,91.8 103.88,90.55 102.57,90.55 102.45,90.42 102.45,89.46 102.32,89.33 102.07,89.33 101.94,89.46 101.94,90.42 101.81,90.55 101.56,90.55 101.43,90.42 101.43,89.46 101.3,89.33 101.05,89.33 100.92,89.46 100.92,90.42 100.8,90.55 100.54,90.55 100.41,90.42 100.41,89.46 100.29,89.33 100.03,89.33 99.91,89.46 99.91,90.42 99.78,90.55 99.53,90.55 99.4,90.42 99.4,89.46 99.27,89.33 99.02,89.33 98.89,89.46 98.89,90.42 98.76,90.55 98.51,90.55 98.38,90.42 98.38,89.46 98.26,89.33 98,89.33 97.87,89.46 97.87,90.42 97.75,90.55 97.49,90.55 97.37,90.42 97.37,89.46 97.24,89.33 96.99,89.33 96.86,89.46 96.86,90.42 96.73,90.55 96.48,90.55 96.35,90.42 96.35,89.46 96.22,89.33 95.97,89.33 95.84,89.46 95.84,90.42 95.72,90.55 95.46,90.55 95.33,90.42 95.33,89.46 95.21,89.33 94.95,89.33 94.83,89.46 94.83,90.42 94.7,90.55 94.45,90.55 94.32,90.42 94.32,89.46 94.19,89.33 93.94,89.33 93.81,89.46 93.81,90.42 93.68,90.55 93.43,90.55 93.3,90.42 93.3,89.46 93.18,89.33 92.92,89.33 92.79,89.46 92.79,90.42 92.67,90.55 92.41,90.55 92.29,90.42 92.29,88.04 92.16,87.91 91.88,87.91 91.76,88.04 91.76,90.42 91.63,90.55 91.38,90.55 91.25,90.42 91.25,88.11 91.12,87.99 90.36,87.99 90.23,87.86 90.23,84.55 90.11,84.42 89.48,84.42 89.36,84.3 89.36,84.04 89.48,83.92 90.11,83.92 90.23,83.79 90.23,83.25 89.92,82.93 89.92,82.17 89.41,81.66 89.41,77.09 v5(89.06,76.74)
PH0: length 8
  TOP w0.203: U4.G1 78.87,143.23 78.87,147.32 v1(78.11,148.08) 77.09,149.1 R19.1
  BOTTOM w0.203: 77.47,148.34 77.72,148.08 v1(78.11,148.08)
PH1: length 16.2
  TOP w0.203: X1.1 73.15,153.67 73.15,149.86 C23.1 v1(74.8,148.21) 75.44,147.57 76.58,147.57 78.46,145.69 78.46,142.94 U4.H1
  BOTTOM w0.127: 73.78,148.89 74.12,148.89 v1(74.8,148.21)
PH2: length 122.5
  TOP w0.127: v3(103.38,118.11) 103.63,118.11 104.34,117.4 CN11.2 ; v5(76.41,140.89) U4.K4
  BOTTOM w0.127: R287.2 91.06,86.31 91.19,86.44 93.14,86.44 93.26,86.56 93.26,88.77 93.39,88.9 93.64,88.9 93.77,88.77 93.77,86.56 93.9,86.44 94.15,86.44 94.28,86.56 94.28,88.77 94.41,88.9 94.66,88.9 94.79,88.77 94.79,88.21 94.91,88.09 95.17,88.09 95.29,88.21 95.29,88.77 95.42,88.9 95.68,88.9 95.8,88.77 95.8,88.21 95.93,88.09 96.18,88.09 96.31,88.21 96.31,88.77 96.44,88.9 96.69,88.9 96.82,88.77 96.82,88.21 96.95,88.09 97.2,88.09 97.33,88.21 97.33,88.77 97.45,88.9 97.71,88.9 97.83,88.77 97.83,88.21 97.96,88.09 98.22,88.09 98.34,88.21 98.34,88.77 98.47,88.9 98.72,88.9 98.85,88.77 98.85,88.21 98.98,88.09 99.23,88.09 99.36,88.21 99.36,88.77 99.49,88.9 99.74,88.9 99.87,88.77 99.87,88.21 99.99,88.09 100.25,88.09 100.37,88.21 100.37,88.77 100.5,88.9 100.76,88.9 100.88,88.77 100.88,88.21 101.01,88.09 101.26,88.09 101.39,88.21 101.39,88.77 101.52,88.9 101.77,88.9 101.9,88.77 101.9,88.21 102.03,88.09 102.28,88.09 102.41,88.21 102.41,88.77 102.53,88.9 102.77,88.9 106.17,92.3 106.17,115.32 v3(103.38,118.11) 102.49,119 102.49,129.41 99.69,132.21 99.69,141.67 96.22,145.15 95.01,145.15 91.19,148.97 89.15,148.97 88.33,148.15 84.95,148.15 83.41,146.61 78.18,146.61 76.71,145.14 76.71,143.38 75.98,142.65 75.98,141.84 75.98,141.52 76.41,141.09 v5(76.41,140.89)
PH3: length 113.9
  TOP w0.102: U13.J8 89.9,75.98 89.9,74.67 89.92,74.66
  TOP w0.127: v3(53.21,118.26) 52.35,117.4 CN10.1 ; v1(90.75,69.49) 89.92,72.06 89.92,74.66
  L4_SIG w0.102: v3(53.21,118.26) 50.67,112.09 50.67,83.92 66.12,68.48 86.56,68.48 86.79,68.25 89.51,68.25 v1(90.75,69.49)
  BOTTOM w0.127: R251.1 65.91,135.38 65.15,134.62 63.14,134.62 59.82,131.29 v3(53.21,118.26)
PH4: length 111.6
  TOP w0.127: U4.H4 v5(78.01,140.09) ; v1(43.43,137.79) 44.4,138.76 45.01,138.76 45.69,139.45 CN5.28 ; R123.2 v1(26.42,100.33)
  L4_SIG w0.102: v1(26.42,100.33) 26.92,99.82 32.46,99.82 33.05,100.41 33.05,101.46 33.15,101.56 33.86,101.56 33.96,101.67 33.96,101.87 33.86,101.97 33.15,101.97 33.05,102.07 33.05,102.28 33.15,102.38 33.86,102.38 33.96,102.48 33.96,102.68 33.86,102.78 33.15,102.78 33.05,102.89 33.05,103.09 33.15,103.19 33.86,103.19 33.96,103.29 33.96,103.5 33.86,103.6 33.15,103.6 33.05,103.7 33.05,103.9 33.15,104 33.86,104 33.96,104.1 33.96,104.31 33.86,104.41 33.15,104.41 33.05,104.51 33.05,104.74 33.15,104.84 33.91,104.84 34.01,104.94 34.01,105.15 33.91,105.25 33.15,105.25 33.05,105.35 33.05,105.55 33.15,105.65 33.91,105.65 34.01,105.76 34.01,105.96 33.91,106.06 33.15,106.06 33.05,106.16 33.05,106.37 33.15,106.47 33.91,106.47 34.01,106.57 34.01,106.77 33.91,106.87 33.15,106.87 33.05,106.98 33.05,107.18 33.15,107.28 33.91,107.28 34.01,107.38 34.01,107.58 33.91,107.69 33.15,107.69 33.05,107.79 33.05,108.08 33.17,108.2 34.9,108.2 38.86,112.17 38.86,138 39.04,138.18 43.05,138.18 v1(43.43,137.79) 43.48,137.74 43.48,136.91 43.74,136.65 54.23,136.65 56.85,134.04 66.42,134.04 68.78,136.4 72.9,136.4 73.79,137.29 76.11,137.29 76.61,137.79 77.01,137.79 77.62,138.4 77.62,139.7 v5(78.01,140.09)
PH5: length 107.7
  TOP w0.102: 89.1,74.66 89.1,75.98 U13.K8
  TOP w0.127: CN10.2 55.58,117.4 v3(54.86,118.11) ; 89.1,74.66 89.1,73.61 87.93,72.44 87.93,69.11 87.58,68.76 v5(87.58,68.73)
  L4_SIG w0.102: v3(54.86,118.11) 53.95,118.11 53.07,117.23 51,112.09 51,84.1 66.27,68.83 87.48,68.83 v5(87.58,68.73)
  BOTTOM w0.127: R254.1 63.2,134.11 61.76,132.68 v3(54.86,118.11)
PH6: length 176.9
  TOP w0.127: CN5.37 42.55,133.1 43.61,132.03 v1(43.61,131.8) ; v1(124.59,141.05) 124.59,143.89 125.35,144.65 v1(125.35,157.35) ; v5(73.21,132.89) U4.P13
  L4_SIG w0.102: v1(124.59,141.05) 124.36,140.82 118.47,140.82 115.06,137.41 113.67,137.41 v1(113.41,137.16) ; v5(73.21,132.89) 73.41,132.69 73.41,129.79 71.5,127.89 66.02,127.89 63.69,130.23 50.32,130.23 49.38,131.17 46.18,131.17 45.06,132.28 44.65,132.28 44.17,131.8 v1(43.61,131.8) ; v1(103.99,156.13) 104.5,155.63 106.93,155.63 108.94,157.63 123.55,157.63 124.26,156.92 124.92,156.92 v1(125.35,157.35)
  BOTTOM w0.127: 111,138.56 111.12,138.43 112.14,138.43 v1(113.41,137.16) 114.53,137.16 SB45.1 ; v1(43.61,131.8) 44.22,131.19 48.41,131.19 49.89,132.66 49.89,138.02 54.76,142.9 54.76,148.16 61.21,154.61 63.42,154.61 66.93,158.12 68.58,158.12 69.01,158.55 73.63,158.55 74.09,159 74.85,159 75.41,158.45 80.24,158.45 80.7,158.9 93.07,158.9 93.51,159.35 101.76,159.35 103.25,157.86 103.25,156.87 v1(103.99,156.13)
PH7: length 166.1
  TOP w0.127: v5(74.01,132.89) U4.N13 ; R45.2 124.08,130.68 124.08,156.84 v1(124.59,157.35) ; CN5.40 v1(44.83,131.83)
  L4_SIG w0.102: v1(124.59,157.35) 124.03,157.91 107.67,157.91 105.84,156.08 v1(104.78,156.08) ; v5(74.01,132.89) 74.01,129.71 71.81,127.51 65.87,127.51 63.53,129.84 50.14,129.84 49.25,130.73 45.92,130.73 v1(44.83,131.83)
  BOTTOM w0.127: v1(104.78,156.08) 103.66,157.2 103.66,157.96 101.94,159.68 93.39,159.68 92.86,159.16 80.57,159.16 80.21,158.8 75.56,158.8 75.1,159.26 73.71,159.26 73.29,158.84 68.79,158.84 68.45,158.5 66.8,158.5 63.27,154.97 61.01,154.97 54.41,148.36 54.41,143.05 49.53,138.18 49.53,132.99 48.36,131.83 v1(44.83,131.83)
PI4: length 125.7
  TOP w0.102: 93.09,74.66 93.09,75.91 U13.F8
  TOP w0.127: 93.09,74.66 93.34,74.4 93.34,70.61 v1(93.98,69.98) ; CN11.17 v3(101.98,107.24) ; v5(82.81,141.69) U4.C3
  L4_SIG w0.102: v3(101.98,107.24) 102.46,107.72 104.85,107.72 106.78,105.79 106.78,81.28 106.68,81.18 106.22,81.18 106.12,81.08 106.12,80.88 106.22,80.78 106.68,80.78 106.78,80.67 106.78,80.47 106.68,80.37 106.22,80.37 106.12,80.27 106.12,80.06 106.22,79.96 106.68,79.96 106.78,79.86 106.78,78.64 106.65,78.51 106.45,78.51 106.32,78.64 106.32,79.4 106.2,79.53 106.08,79.53 105.98,79.43 105.98,78.61 105.87,78.51 105.67,78.51 105.57,78.61 105.57,79.43 105.47,79.53 105.26,79.53 105.16,79.43 105.16,78.61 105.06,78.51 104.86,78.51 104.76,78.61 104.76,79.43 104.65,79.53 104.45,79.53 104.35,79.43 104.35,78.61 104.25,78.51 104.05,78.51 103.94,78.61 103.94,79.43 103.84,79.53 103.64,79.53 103.54,79.43 103.54,78.61 103.44,78.51 103.23,78.51 103.13,78.61 103.13,79.43 103.03,79.53 102.83,79.53 102.72,79.43 102.72,78.61 102.62,78.51 102.42,78.51 102.32,78.61 102.32,79.43 102.22,79.53 102.01,79.53 101.91,79.43 101.91,78.61 101.81,78.51 101.61,78.51 101.51,78.61 101.51,79.43 101.4,79.53 101.2,79.53 101.1,79.43 101.1,78.61 101,78.51 100.79,78.51 100.69,78.61 100.69,79.43 100.59,79.53 99.87,79.53 99.75,79.4 99.75,75.23 94.49,69.98 v1(93.98,69.98)
  BOTTOM w0.127: v5(82.81,141.69) 83.52,141.69 84.5,142.67 86.44,142.67 88.01,141.1 90.55,141.1 91.44,140.21 91.44,139.6 91.84,139.21 92.41,139.21 92.84,138.78 92.84,133.35 92.2,132.72 92.2,116.71 101.68,107.24 v3(101.98,107.24)
PI5: length 124.5
  TOP w0.102: 97.73,78.36 94.87,78.36 93.09,80.14 93.09,80.64 92.66,81.08 U13.F2
  TOP w0.127: CN11.15 v3(101.98,108.51) ; v1(100.2,78.74) 99.69,78.74 99.31,78.36 97.73,78.36 ; v5(82.01,141.69) U4.D3
  L4_SIG w0.102: v3(101.98,108.51) 101.98,108.13 102.08,108.03 105.26,108.03 107.16,106.12 107.16,76.95 107.04,76.83 106.88,76.83 106.76,76.95 106.76,78.08 106.63,78.21 106.41,78.21 106.3,78.11 106.3,76.95 106.19,76.83 106.02,76.83 105.9,76.95 105.9,78.11 105.8,78.21 105.59,78.21 105.49,78.11 105.49,76.95 105.37,76.83 105.2,76.83 105.09,76.95 105.09,78.11 104.98,78.21 104.78,78.21 104.68,78.11 104.68,76.95 104.56,76.83 104.39,76.83 104.27,76.95 104.27,78.11 104.17,78.21 103.97,78.21 103.87,78.11 103.87,76.95 103.75,76.83 103.58,76.83 103.46,76.95 103.46,78.11 103.36,78.21 103.16,78.21 103.05,78.11 103.05,76.95 102.93,76.83 102.77,76.83 102.65,76.95 102.65,78.11 102.55,78.21 102.34,78.21 102.24,78.11 102.24,76.95 102.12,76.83 101.95,76.83 101.83,76.95 101.83,78.11 101.73,78.21 101.53,78.21 101.43,78.11 101.43,76.95 101.31,76.83 101.14,76.83 101.02,76.95 101.02,78.08 100.89,78.21 100.71,78.21 100.58,78.08 100.58,76.96 100.46,76.83 100.25,76.83 100.13,76.96 100.13,78.66 v1(100.2,78.74)
  BOTTOM w0.127: v5(82.01,141.69) 82.41,142.09 83.34,142.09 84.3,143.05 86.6,143.05 88.04,141.6 91.12,141.6 91.46,141.27 91.46,141.27 93.6,139.13 93.6,132.84 92.96,132.21 92.96,117.4 101.85,108.51 v3(101.98,108.51)
PI8: length 225.6
  TOP w0.127: CN6.9 111.15,150.88 111.73,151.46 v1(111.89,151.46) ; U4.C2 v5(82.81,142.49)
  L4_SIG w0.102: v1(134.37,107.57) 134.11,107.57 132.54,105.99 132.54,102.44 117.12,87.02 117.12,78.19 73.8,34.87 70.03,34.87 69.34,35.56 56.29,35.56 v1(55.8,36.04) ; v5(82.81,142.49) 82.81,144.53 85.85,147.57 90.3,147.57 91.31,148.59 92.84,148.59 96.47,152.22 109.55,152.22 110.26,151.51 111.84,151.51 v1(111.89,151.46) 112.57,151.46 113.06,151.94 127.23,151.94 v1(128.27,152.98)
  BOTTOM w0.127: R295.1 54.99,33.4 54.99,35.23 v1(55.8,36.04) ; v1(134.37,107.57) 134.21,107.72 134.21,118.39 136.73,120.9 136.73,124.46 131.65,129.54 131.65,149.71 128.37,152.98 v1(128.27,152.98)
PI11: length 116.4
  TOP w0.127: v1(44.09,153.42) 44.09,153.64 45.18,154.73 45.18,155.47 45.67,155.96 CN5.2 ; R124.2 v1(27.94,100.33) ; U4.F3 v5(80.41,141.69)
  L4_SIG w0.102: v5(80.41,141.69) 80.14,141.69 79.76,141.3 79.27,141.3 79.12,141.45 79.12,142.54 78.18,143.48 77.6,143.48 77.11,143.97 77.11,146.2 75.87,147.45 73.46,147.45 69.52,151.38 55.12,151.38 52.96,153.54 44.22,153.54 v1(44.09,153.42) 43.64,152.96 41.71,152.96 35.84,147.09 35.84,145.82 33.63,143.61 33.63,139.42 34.04,139.01 34.04,129.03 31.62,126.62 31.62,119.38 34.24,116.76 34.24,112.73 31.24,109.73 31.24,102.11 30.1,100.97 28.68,100.97 28.55,101.09 28.55,102.03 28.42,102.16 28.07,102.16 27.94,102.03 v1(27.94,100.33)
PI12: length 203.2
  TOP w0.127: U4.E3 v5(81.21,141.69) ; v1(111.89,152.32) 111.28,152.32 111.1,152.15 CN6.7 ; v1(78.42,29.08) CN20.26
  L4_SIG w0.102: v1(111.89,152.32) 110.49,152.32 109.96,152.86 92.66,152.86 90.32,150.52 90.32,149.63 89.28,148.59 85.72,148.59 81.65,144.52 81.65,142.13 v5(81.21,141.69)
  BOTTOM w0.127: v1(111.89,152.32) 112.6,152.32 113.28,153.01 113.86,153.01 114.31,152.56 114.31,152.07 125.58,140.79 125.58,117.3 120.47,112.19 120.47,97.61 119.3,96.44 119.3,73.9 115.6,70.2 113.12,70.2 90.42,47.5 90.42,28.45 88.77,26.8 80.71,26.8 v1(78.42,29.08)
PI13: length 212.5
  TOP w0.127: v1(117.65,152.81) 117.65,154.86 116.56,155.96 CN6.2 ; U4.G3 v5(79.61,141.69) ; v1(77.15,29.08) CN20.28
  L4_SIG w0.102: v1(117.65,152.81) 114.51,152.81 113.95,153.37 110.69,153.37 110.49,153.57 91.97,153.57 88.39,149.99 85.09,149.99 80.9,145.8 80.9,144.91 80.04,144.04 80.04,142.18 79.61,141.75 v5(79.61,141.69)
  BOTTOM w0.127: v1(77.15,29.08) 77.22,29.08 80.26,26.04 89.41,26.04 91.57,28.19 91.57,46.99 113.82,69.24 115.92,69.24 120.23,73.55 120.23,96.07 121.11,96.95 121.11,111.68 126.21,116.79 126.21,141.35 117.65,149.91 v1(117.65,152.81)
PI14: length 174.1
  TOP w0.127: CN20.32 74.61,22.8 v1(74.42,22.61) ; v1(51.69,137.41) 51.18,136.91 CN5.32 45.09,136.91 v1(44.7,137.29)
  BOTTOM w0.127: R225.1 61.2,152.27 56.39,147.47 56.39,142.11 v1(51.69,137.41) ; v1(74.42,22.61) 70.7,22.61 67.69,25.61 67.69,47.55 62.48,52.76 62.48,61.09 54.36,69.22 54.36,81 45.06,90.3 45.06,108.74 38.35,115.44 38.35,125.73 37.47,126.62 37.47,131.4 39.39,133.32 44.93,133.32 45.34,133.73 45.34,134.59 44.07,135.86 44.07,136.65 v1(44.7,137.29)
PK7: length 201.8
  TOP w0.127: v1(89.92,44.07) 94.36,39.62 94.36,23.62 92.84,22.1 84.84,22.1 R192.2 ; U4.C4 v5(82.81,140.89) ; CN6.8 113.89,152.15 113.39,151.64 v1(113.39,151.49)
  L4_SIG w0.102: v1(113.39,151.49) 113.23,151.49 112.78,151.03 110.01,151.03 108.33,149.35 94.74,149.35 93.09,147.7 91.57,147.7 87.88,144.02 85.98,144.02 82.85,140.89 v5(82.81,140.89)
  BOTTOM w0.127: v1(89.92,44.07) 89.92,48.39 112.95,71.42 115.39,71.42 118.08,74.12 118.08,110.92 124.92,117.75 124.92,138.83 118.71,145.03 118.71,146.27 113.49,151.49 v1(113.39,151.49)
PWR_ENN: length 12.9
  TOP w0.127: R159.2 36.96,47.85 36.96,38.89 36.94,38.87 U21.28
  TOP w0.254: U17.3 R159.2
RESET#: length 372.7
  TOP w0.127: CN20.36 72.07,26.23 73.28,25.02 73.28,22.86 71.5,21.08 54.74,21.08 51.69,24.13 D16.2 v1(50.67,25.04) ; v1(51.18,12.32) C99.2 51.24,10.99 B1.3 B1.2 ; U21.18 37.24,33.41 v1(36.83,32.99) ; v1(22.61,97.79) 21.59,98.81 21.59,99.33 20.71,100.2 R127.2 ; U6.29 133.01,121.04 133.58,120.47 v1(133.76,120.47) ; v1(31.24,139.06) 30.27,139.06 D2.1 ; v5(77.5,144.25) 77.54,144.21 77.54,142.96 U4.J1 ; R104.2 126.62,106.81 127.94,106.81 v1(129.03,107.89)
  L4_SIG w0.102: v1(120.5,153.24) 120.12,153.62 111.28,153.62 110.97,153.92 91.59,153.92 87.91,150.24 83.69,150.24 82.04,148.59 82.04,147.57 80.39,145.92 80.39,144.91 79.45,143.97 77.78,143.97 v5(77.5,144.25) 77.39,144.35 77.39,146.41 76.09,147.71 73.65,147.71 69.52,151.84 55.3,151.84 53.24,153.9 43.76,153.9 43.28,153.42 v1(43.26,153.42) 41.6,153.42 35.46,147.28 35.46,145.95 31.24,141.73 v1(31.24,139.06) 31.24,135.51 30.86,135.13 30.86,126.87 22.05,118.06 22.05,114.35 v1(23.14,113.26) ; v1(50.67,25.04) 50.67,26.8 48.39,29.08 41.38,29.08 37.47,32.99 v1(36.83,32.99) 34.39,32.99 30.81,36.57 30.81,61.54 27.56,64.79 27.56,86.61 27.33,86.84 27.33,93.07 v1(22.61,97.79)
  BOTTOM w0.127: v1(129.03,107.89) 130.27,107.89 133.1,110.72 133.1,119.81 v1(133.76,120.47) 134.26,120.98 134.26,122.4 132.74,123.93 132.74,125.81 129.13,129.41 129.13,144.6 v1(120.5,153.24) ; v1(23.14,113.26) 22.02,112.14 22.02,98.37 v1(22.61,97.79) ; v1(51.18,12.32) 51.18,13.97 53.72,16.51 53.72,21.21 50.67,24.26 v1(50.67,25.04) ; v1(43.26,153.42) R224.1
STL_USB_DM: length 26.1
  TOP w0.155: U21.32 34.94,38.84 34.88,38.9 34.88,40.05 33.27,41.66 24.38,41.66 22.86,40.13 22.86,37.08 20.76,34.99 16.83,34.99 R166.2
STL_USB_DP: length 25.5
  TOP w0.155: U21.33 34.44,38.84 34.5,38.9 34.5,39.89 33.12,41.27 24.54,41.27 23.24,39.97 23.24,36.93 20.92,34.61 16.83,34.61 R169.2
STLINK_RX: length 28.6
  TOP w0.127: JP20.3 45.47,13.97 CN23.1 46.1,17.14 46.1,26.09 41.28,30.9 U21.13
STLINK_TX: length 26.4
  TOP w0.127: U21.12 42.07,29.3 45.47,25.91 45.47,19.05 CN23.2
  BOTTOM w0.127: JP14.3 51.44,18.92 45.34,18.92 CN23.2
STM_JTCK_SWCLK: length 6.2
  TOP w0.127: CN18.3 26.92,35.56 29.46,35.56 30.31,36.41 U21.37
STM_JTMS_SWDIO: length 9.9
  TOP w0.127: CN18.1 27.18,37.85 31.37,37.85 32.38,36.83 33.53,36.83 33.94,37.24 U21.34
STM_RST: length 6.4
  TOP w0.127: v1(36.83,31.62) 35.94,30.73 U21.7
  BOTTOM w0.127: R297.1 SB64.2 C175.2 v1(36.83,31.62)
T_JTDO: length 265
  TOP w0.127: R99.2 127.13,108.58 v1(127.38,108.33) ; U21.31 v1(35.44,35.94) 35.44,33.52 36.42,32.54 39.34,32.54 39.48,32.41 U21.16 ; v1(147.57,139.95) 147.57,139.83 147.45,139.7 147.45,135 146.43,133.99 146.43,130.43 148.08,128.78 150.14,128.78 151.26,127.67 151.26,126.24 151.69,125.81 v1(151.69,125.78)
  L4_SIG w0.102: v1(147.57,139.95) 147.47,139.95 146.3,138.79 145.9,138.79 140.11,144.58 133.15,144.58 120.45,131.88 113.39,131.88 112.88,132.38 103.84,132.38 103.02,131.57 98.93,131.57 JP4.1 ; v1(35.44,35.94) 36.17,35.2 38.2,35.2 40.51,32.89 41.27,32.89 41.53,32.64 41.53,32.28 41.92,31.89 48.66,31.89 50.29,33.53 50.29,38.15 52.22,40.08 54.91,40.08 56.01,38.99 72.82,38.99 76.3,42.47 78.21,42.47 115.11,79.38 115.11,87.53 129.77,102.18 129.77,105.16 127.38,107.54 v1(127.38,108.33) 128.52,109.47 131.95,109.47 134.11,111.63 135.53,111.63 140,116.1 142.74,116.1 146.43,119.79 149.96,119.79 151.69,121.52 v1(151.69,125.78)
